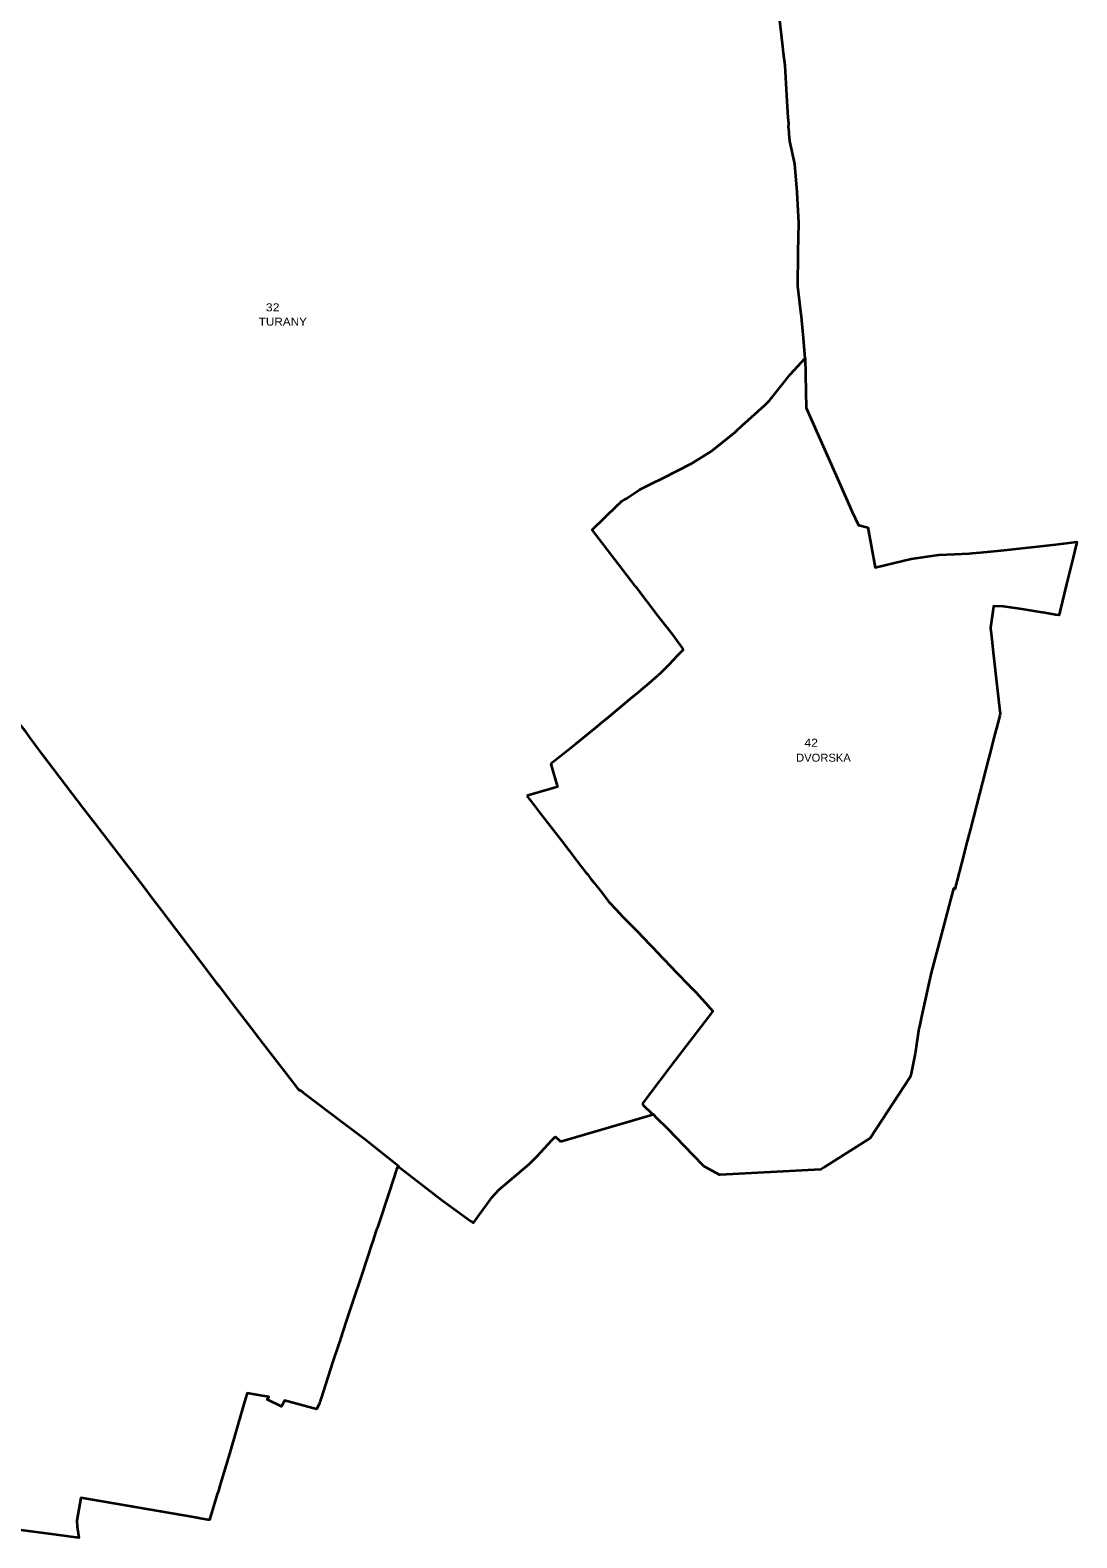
# Model space of a CAD drawing. Extents: x -610940 to -588976, y -1170376 to -1149800.
# Drawn here: x -594465 to -591184, y -1170169 to -1165441 of the extents above; entities that cross this region are included whole.
import ezdxf

# ---------------------------------------------------------------- set-up
doc = ezdxf.new("R2010")
doc.units = 0
doc.header["$LTSCALE"] = 10
doc.layers.add('54', color=7, linetype='Continuous', lineweight=35)
doc.layers.add('55', color=7, linetype='Continuous')
doc.layers.add('56', color=7, linetype='Continuous')

msp = doc.modelspace()

# ---------------------------------------------------------------- linework, layer by layer
at = {"layer": '54'}
for p, q in [((-592686.88, -1167623.55), (-592677.78, -1167616)), ((-592677.78, -1167616), (-592651.16, -1167593.93)), ((-592692.92, -1167628.42), (-592686.88, -1167623.55)), ((-592833.14, -1167740.93), (-592831.81, -1167745.52)), ((-592831.81, -1167745.52), (-592825.4, -1167767.67)), ((-592825.4, -1167767.67), (-592818.01, -1167793.21)), ((-592904.8, -1167841.32), (-592907.92, -1167842.24)), ((-592907.92, -1167842.24), (-592898.05, -1167854.98)), ((-592832.66, -1167820.13), (-592904.8, -1167841.32)), ((-592775.62, -1168013.79), (-592758.68, -1168035.81)), ((-592758.68, -1168035.81), (-592723.56, -1168081.74)), ((-594152.38, -1168071.22), (-594141.71, -1168085.21)), ((-592723.56, -1168081.74), (-592718.12, -1168087.8)), ((-592718.12, -1168087.8), (-592712.39, -1168095.19)), ((-592712.39, -1168095.19), (-592708.19, -1168100.61)), ((-592510.07, -1168320.81), (-592501.22, -1168330.2)), ((-593882.76, -1168426.16), (-593872.85, -1168439.19)), ((-592348.88, -1168489.46), (-592333.19, -1168507.32)), ((-593632.16, -1168752.68), (-593629.9, -1168755.63)), ((-592522.67, -1168776.23), (-592523.86, -1168777.8)), ((-592520.55, -1168773.42), (-592522.67, -1168776.23)), ((-592803.13, -1168925.28), (-592659.06, -1168883.5)), ((-592806.04, -1168922.58), (-592803.13, -1168925.28)), ((-593311.91, -1169003.8), (-593304.6, -1169009.4)), ((-593304.6, -1169009.4), (-593276.87, -1169030.65))]:
    msp.add_line(p, q, dxfattribs=at)
for points in [[(-592482.05, -1166845.74), (-592389.81, -1166798.63), (-592328.86, -1166761.31), (-592255.43, -1166701.95), (-592250.84, -1166697.66), (-592232.62, -1166680.41), (-592162.96, -1166618.25), (-592146.27, -1166601.39), (-592140.63, -1166594.36), (-592138.72, -1166591.52), (-592082.8, -1166520.93), (-592035.24, -1166469.1), (-592042.22, -1166394.99), (-592047.13, -1166338.38), (-592047.64, -1166332.98), (-592058.69, -1166244.07), (-592058.12, -1166220.97), (-592057.69, -1166164.22), (-592057.67, -1166136.14), (-592056.33, -1166092.25), (-592055.12, -1166045.14), (-592060.96, -1165949.01), (-592068.41, -1165859.81), (-592083.67, -1165788.86), (-592085.7, -1165765.77), (-592086.05, -1165761.58), (-592087.07, -1165749.31), (-592087.38, -1165745.53), (-592087.23, -1165733.87), (-592088.44, -1165714.6), (-592093.17, -1165645.39), (-592098, -1165551.28), (-592103.15, -1165513.46), (-592106.01, -1165492.02), (-592122.19, -1165345.55)], [(-592035.24, -1166469.1), (-592032.38, -1166624.8), (-591926.05, -1166865.27), (-591888.51, -1166951.23), (-591868.8, -1166992.82), (-591862.75, -1166994.32), (-591843.75, -1166999.03), (-591839.36, -1167000.12), (-591815.84, -1167125.61), (-591729.12, -1167104.69), (-591702.88, -1167098.72), (-591616.2, -1167086.38), (-591615.78, -1167086.36), (-591566.23, -1167083.58), (-591520.96, -1167081.75), (-591511.64, -1167081.26), (-591487.02, -1167079.24), (-591412.12, -1167071.86), (-591250.26, -1167053.7), (-591183.83, -1167045.3), (-591184.98, -1167050.13), (-591195.59, -1167094.45), (-591216.11, -1167178.3), (-591236.89, -1167264.42), (-591237.5, -1167266.94), (-591237.59, -1167267.31), (-591238.78, -1167272.23), (-591238.9, -1167272.74), (-591239.58, -1167275.58), (-591250.3, -1167274.05), (-591283.73, -1167268.29), (-591299.1, -1167266.04), (-591355.34, -1167256.27), (-591413.57, -1167248.19), (-591444.9, -1167247.26), (-591445.24, -1167249.64), (-591454.73, -1167314.78), (-591454.76, -1167315.69), (-591449.42, -1167360.86), (-591447.09, -1167383.36)], [(-592543.16, -1166876.06), (-592515.82, -1166862.5), (-592482.05, -1166845.74)], [(-592599.6, -1166911.54), (-592595.71, -1166909.35), (-592554.36, -1166881.62), (-592543.16, -1166876.06)], [(-592567.18, -1167185.03), (-592580.05, -1167168.6), (-592607.28, -1167132.73), (-592703.17, -1167007.35), (-592623.64, -1166930.33)], [(-592623.64, -1166930.33), (-592614.94, -1166921.9), (-592612.05, -1166919.1)], [(-592612.05, -1166919.1), (-592607.95, -1166916.59), (-592601.19, -1166912.44), (-592599.6, -1166911.54)], [(-592567.18, -1167185.03), (-592531.78, -1167232.16), (-592496.01, -1167279.81), (-592453.06, -1167335.24), (-592420.49, -1167380.24), (-592419.98, -1167381.09), (-592418.52, -1167383.53), (-592435.22, -1167401.04), (-592463.79, -1167431.68), (-592490.63, -1167458.15), (-592497.19, -1167464.15)], [(-591447.09, -1167383.36), (-591441.92, -1167428.52), (-591436.26, -1167475.52), (-591424.92, -1167576.19), (-591423.99, -1167583.02), (-591425.64, -1167589.54), (-591435.92, -1167630.19), (-591442.84, -1167656.19), (-591454.59, -1167702.86), (-591460.59, -1167725.69), (-591517.09, -1167944.86), (-591531.64, -1167999.81), (-591538.41, -1168026.11), (-591566.08, -1168134.17), (-591570.83, -1168132.89), (-591619.33, -1168318.7), (-591640.91, -1168397.03), (-591668.84, -1168524.82), (-591678.52, -1168569.11), (-591678.99, -1168571.28), (-591689.83, -1168643.28), (-591691.12, -1168649.88), (-591693.22, -1168660.53), (-591702.38, -1168707.16), (-591705.05, -1168720.72), (-591705.2, -1168721.51), (-591831.7, -1168915.65), (-591977.41, -1169007.78), (-591986.45, -1169013.15), (-592301.74, -1169030.28), (-592303.83, -1169030.02), (-592348.08, -1169006.36), (-592352.78, -1169003.2), (-592387.15, -1168968.13), (-592466.14, -1168886.44), (-592500.15, -1168852.61), (-592512.19, -1168840.45), (-592513.24, -1168841.14)], [(-592651.16, -1167593.93), (-592619.05, -1167567.04), (-592585.05, -1167538.93), (-592556.63, -1167515.65), (-592523.16, -1167487.91), (-592497.19, -1167464.15)], [(-594500.69, -1167614.05), (-594483.55, -1167636.45), (-594467.41, -1167658.52), (-594451.96, -1167679.71), (-594443.09, -1167691.79)], [(-592833.14, -1167740.93), (-592809.25, -1167722.07), (-592789.03, -1167705.7), (-592753.77, -1167677.38), (-592719.85, -1167650.16), (-592692.92, -1167628.42)], [(-594443.09, -1167691.79), (-594437.13, -1167699.65), (-594430.37, -1167708.55), (-594297.99, -1167882.86)], [(-592818.01, -1167793.21), (-592811.98, -1167814.05), (-592832.66, -1167820.13)], [(-592898.05, -1167854.98), (-592886.41, -1167870), (-592864.09, -1167899.06), (-592841.25, -1167928.74), (-592819.8, -1167956.71), (-592797.83, -1167984.98), (-592778, -1168010.7), (-592775.62, -1168013.79)], [(-594297.99, -1167882.86), (-594261.27, -1167929.56), (-594212.03, -1167993.54), (-594163.86, -1168056.16), (-594152.38, -1168071.22)], [(-594141.71, -1168085.21), (-594138.88, -1168088.93), (-594107.71, -1168129.8), (-594081.31, -1168164.43), (-594059.75, -1168192.78), (-594010.58, -1168257.42)], [(-592708.19, -1168100.61), (-592698.06, -1168113.66), (-592677.41, -1168139.79), (-592657.09, -1168165.88), (-592651.89, -1168173.44), (-592629.51, -1168197.69), (-592608.15, -1168220), (-592585.3, -1168243.33), (-592563.82, -1168264.66), (-592542.24, -1168287.45), (-592521.37, -1168308.82), (-592510.07, -1168320.81)], [(-594010.58, -1168257.42), (-593930.86, -1168362.88), (-593882.76, -1168426.16)], [(-592501.22, -1168330.2), (-592478.77, -1168353.56), (-592437.88, -1168396.45), (-592400.34, -1168435.31), (-592378.25, -1168457.88), (-592357.97, -1168479.11), (-592348.88, -1168489.46)], [(-593872.85, -1168439.19), (-593832.02, -1168492.91), (-593761.91, -1168584.4)], [(-592333.19, -1168507.32), (-592324.58, -1168517.13), (-592338.3, -1168534.93)], [(-592338.3, -1168534.93), (-592455.5, -1168687.07), (-592458.76, -1168691.42), (-592520.55, -1168773.42)], [(-593761.91, -1168584.4), (-593759.79, -1168587.12), (-593735.64, -1168618.14)], [(-593735.64, -1168618.14), (-593685.21, -1168683.4), (-593632.16, -1168752.68)], [(-593629.9, -1168755.63), (-593621.78, -1168766.23), (-593620.31, -1168763.22), (-593616.51, -1168765.98), (-593608.85, -1168773.33), (-593605.41, -1168775.66), (-593601.18, -1168778.83)], [(-593601.18, -1168778.83), (-593527.64, -1168833.75), (-593484.99, -1168866.64), (-593418.4, -1168916.58), (-593346.12, -1168973.57), (-593310.31, -1169001.54), (-593311.91, -1169003.8)], [(-592523.86, -1168777.8), (-592544.68, -1168805.43), (-592544.47, -1168810.04), (-592543.13, -1168811.37)], [(-592659.06, -1168883.5), (-592513.52, -1168841.3), (-592513.24, -1168841.14)], [(-592543.13, -1168811.37), (-592516.06, -1168838.33), (-592513.24, -1168841.14)], [(-593056.85, -1169154.84), (-593033.7, -1169123.11), (-593018.13, -1169101.73), (-592995.82, -1169077.26), (-592900.19, -1168995.27), (-592875.33, -1168971.3), (-592829.4, -1168921.39), (-592827.58, -1168919.5), (-592826.42, -1168918.37)], [(-592826.42, -1168918.37), (-592821.51, -1168913.58), (-592819.66, -1168911.78)], [(-592819.66, -1168911.78), (-592818.69, -1168910.83), (-592806.04, -1168922.58)], [(-593311.91, -1169003.8), (-593313.88, -1169006.05), (-593316.32, -1169013.56), (-593338.79, -1169081.77), (-593376.64, -1169194.9), (-593379.09, -1169201.58), (-593388.72, -1169230.95), (-593389.37, -1169232.91), (-593394.01, -1169246.89), (-593425.68, -1169342.35), (-593454.47, -1169429.54), (-593470.02, -1169476.88), (-593486.76, -1169527.88), (-593490.49, -1169539.24), (-593491.9, -1169543.42), (-593493.84, -1169549.14), (-593497.65, -1169560.39), (-593516.95, -1169618.88), (-593553.33, -1169730.73), (-593555.02, -1169736.27), (-593556.33, -1169740.52), (-593556.87, -1169742.31), (-593558.04, -1169746.14), (-593558.95, -1169749.08), (-593567.94, -1169765.18), (-593668.36, -1169737.66), (-593676.97, -1169756.57), (-593721.76, -1169734.3), (-593717.45, -1169726.62), (-593749.85, -1169721), (-593785.26, -1169714.81), (-593790.35, -1169732.07), (-593798.56, -1169759.91), (-593840.71, -1169904.98), (-593868.49, -1169997.67), (-593876.4, -1170023.97), (-593878.92, -1170032.02), (-593902.91, -1170112.57), (-593906.16, -1170112.15), (-593908.59, -1170111.73)], [(-593276.87, -1169030.65), (-593175.62, -1169108.24), (-593102.21, -1169161.72)], [(-593102.21, -1169161.72), (-593083.51, -1169175.34), (-593075.65, -1169180.61), (-593056.85, -1169154.84)], [(-593908.59, -1170111.73), (-593919.66, -1170109.65), (-593932.57, -1170107.39), (-593936.87, -1170106.64), (-593953.57, -1170103.72), (-594306.3, -1170042.6), (-594318.98, -1170114.24), (-594318.24, -1170133.14), (-594312.79, -1170168.54), (-594320.31, -1170167.79), (-594320.6, -1170167.75), (-594374.82, -1170160.3), (-594526, -1170140.27)]]:
    msp.add_lwpolyline(points, dxfattribs=at)

# ---------------------------------------------------------------- texts
at = {"layer": '55'}
for s, width, p in [('TURANY ', 1.1, (-593748.77, -1166367.41)), ('DVORSKA ', 1.05, (-592064.1, -1167734.76))]:
    msp.add_text(s, height=25, dxfattribs=dict(at, width=width)).set_placement(p)
at = {"layer": '56', "width": 1.15}
for s, p in [('32 ', (-593726.47, -1166322.7)), ('42 ', (-592038.1, -1167687.94))]:
    msp.add_text(s, height=25, dxfattribs=at).set_placement(p)

doc.saveas('drawing.dxf')
